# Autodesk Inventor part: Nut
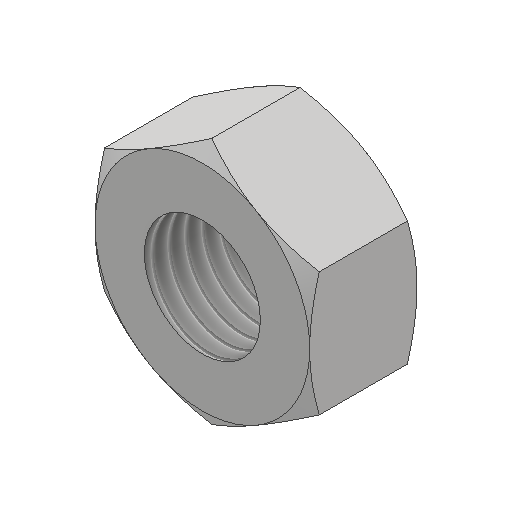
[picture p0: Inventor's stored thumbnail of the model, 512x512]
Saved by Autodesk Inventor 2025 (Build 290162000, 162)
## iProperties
Created: 2016-05
Part Number: Nut
Material: Generic
Document SubType Name: Modeling
Designer: CADCIM
Density: 1 g/cm^3
Appearance: Default
Author: CADCIM
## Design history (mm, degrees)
sketch "Sketch1"
  geometry: L1 (0, -18.475)-(-16, -9.238); L2 (-16, -9.238)-(-16, 9.238); L3 (-16, 9.238)-(0, 18.475); L4 (0, 18.475)-(16, 9.238); L5 (16, 9.238)-(16, -9.238); L6 (16, -9.238)-(0, -18.475); 2 further points
  constraints: 12 end point, 1 coincident, 13 other
  dimensions: "d0" = 32 distance between parallel lines of L2 L5
extrude "Extrusion1" new body sketch "Sketch1" distance "d1" = 16; taper "d2" = 0 deg
sketch "Sketch2"
  geometry: L1 (16, -9.238)-(16, 9.238) reference; C1 r 16 at (0, 0); 1 further point
  constraints: 1 centre point, 1 coincident, 1 tangent
extrude "Extrusion2" sketch "Sketch2" distance "d3" = 16; taper "d4" = 60 deg
sketch "Sketch3"
  geometry: L1 (0, -18.475)-(16, -9.238) reference; C1 r 16 at (0, 0); 1 further point
  constraints: 1 centre point, 1 coincident, 1 tangent
extrude "Extrusion3" sketch "Sketch3" distance "d5" = 16; taper "d6" = 60 deg
hole "Hole1" diameter "d9" = 17.294; stored, may be unused: countersink angle "d13" = 90 deg, drill point angle "d15" = 118 deg; dims "d7" = 10, "d8" = 10, "d10" = 40, "d11" = 4, "d12" = 2, "d14" = 51.2
body "Solid1"
